// Mitsubishi GX Works2 project: 2.正反转互锁   PLC: FX3U/FX3UC

PROGRAM MAIN
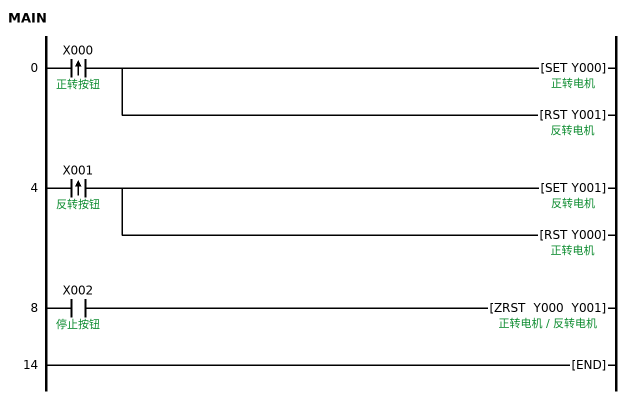
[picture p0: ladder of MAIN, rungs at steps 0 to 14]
0     LDP     X000  ; 正转按钮
      SET     Y000  ; 正转电机
      RST     Y001  ; 反转电机
4     LDP     X001  ; 反转按钮
      SET     Y001  ; 反转电机
      RST     Y000  ; 正转电机
8     LD      X002  ; 停止按钮
      ZRST    Y000 Y001
14    END
END_PROGRAM
